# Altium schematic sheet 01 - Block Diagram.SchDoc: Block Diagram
size A3; PageSetup: Record=PageOptions¦CenterHorizontal=True¦CenterVertical=True¦PrintScale=0.70¦XCorrection=1.00¦YCorrection=1.00¦PrintKind=0¦BorderSize=5000000¦LeftOffset=0¦BottomOffset=0¦Orientation=2¦PaperLength=4200¦PaperWidth=2970¦Scale=100¦PaperSource=7¦PrintQuality=600¦MediaType=1¦DitherType=10¦PaperKind=A4¦PrintScaleMode=1; Author: Juan Anzola; SheetNumber: 1; SheetTotal: 20
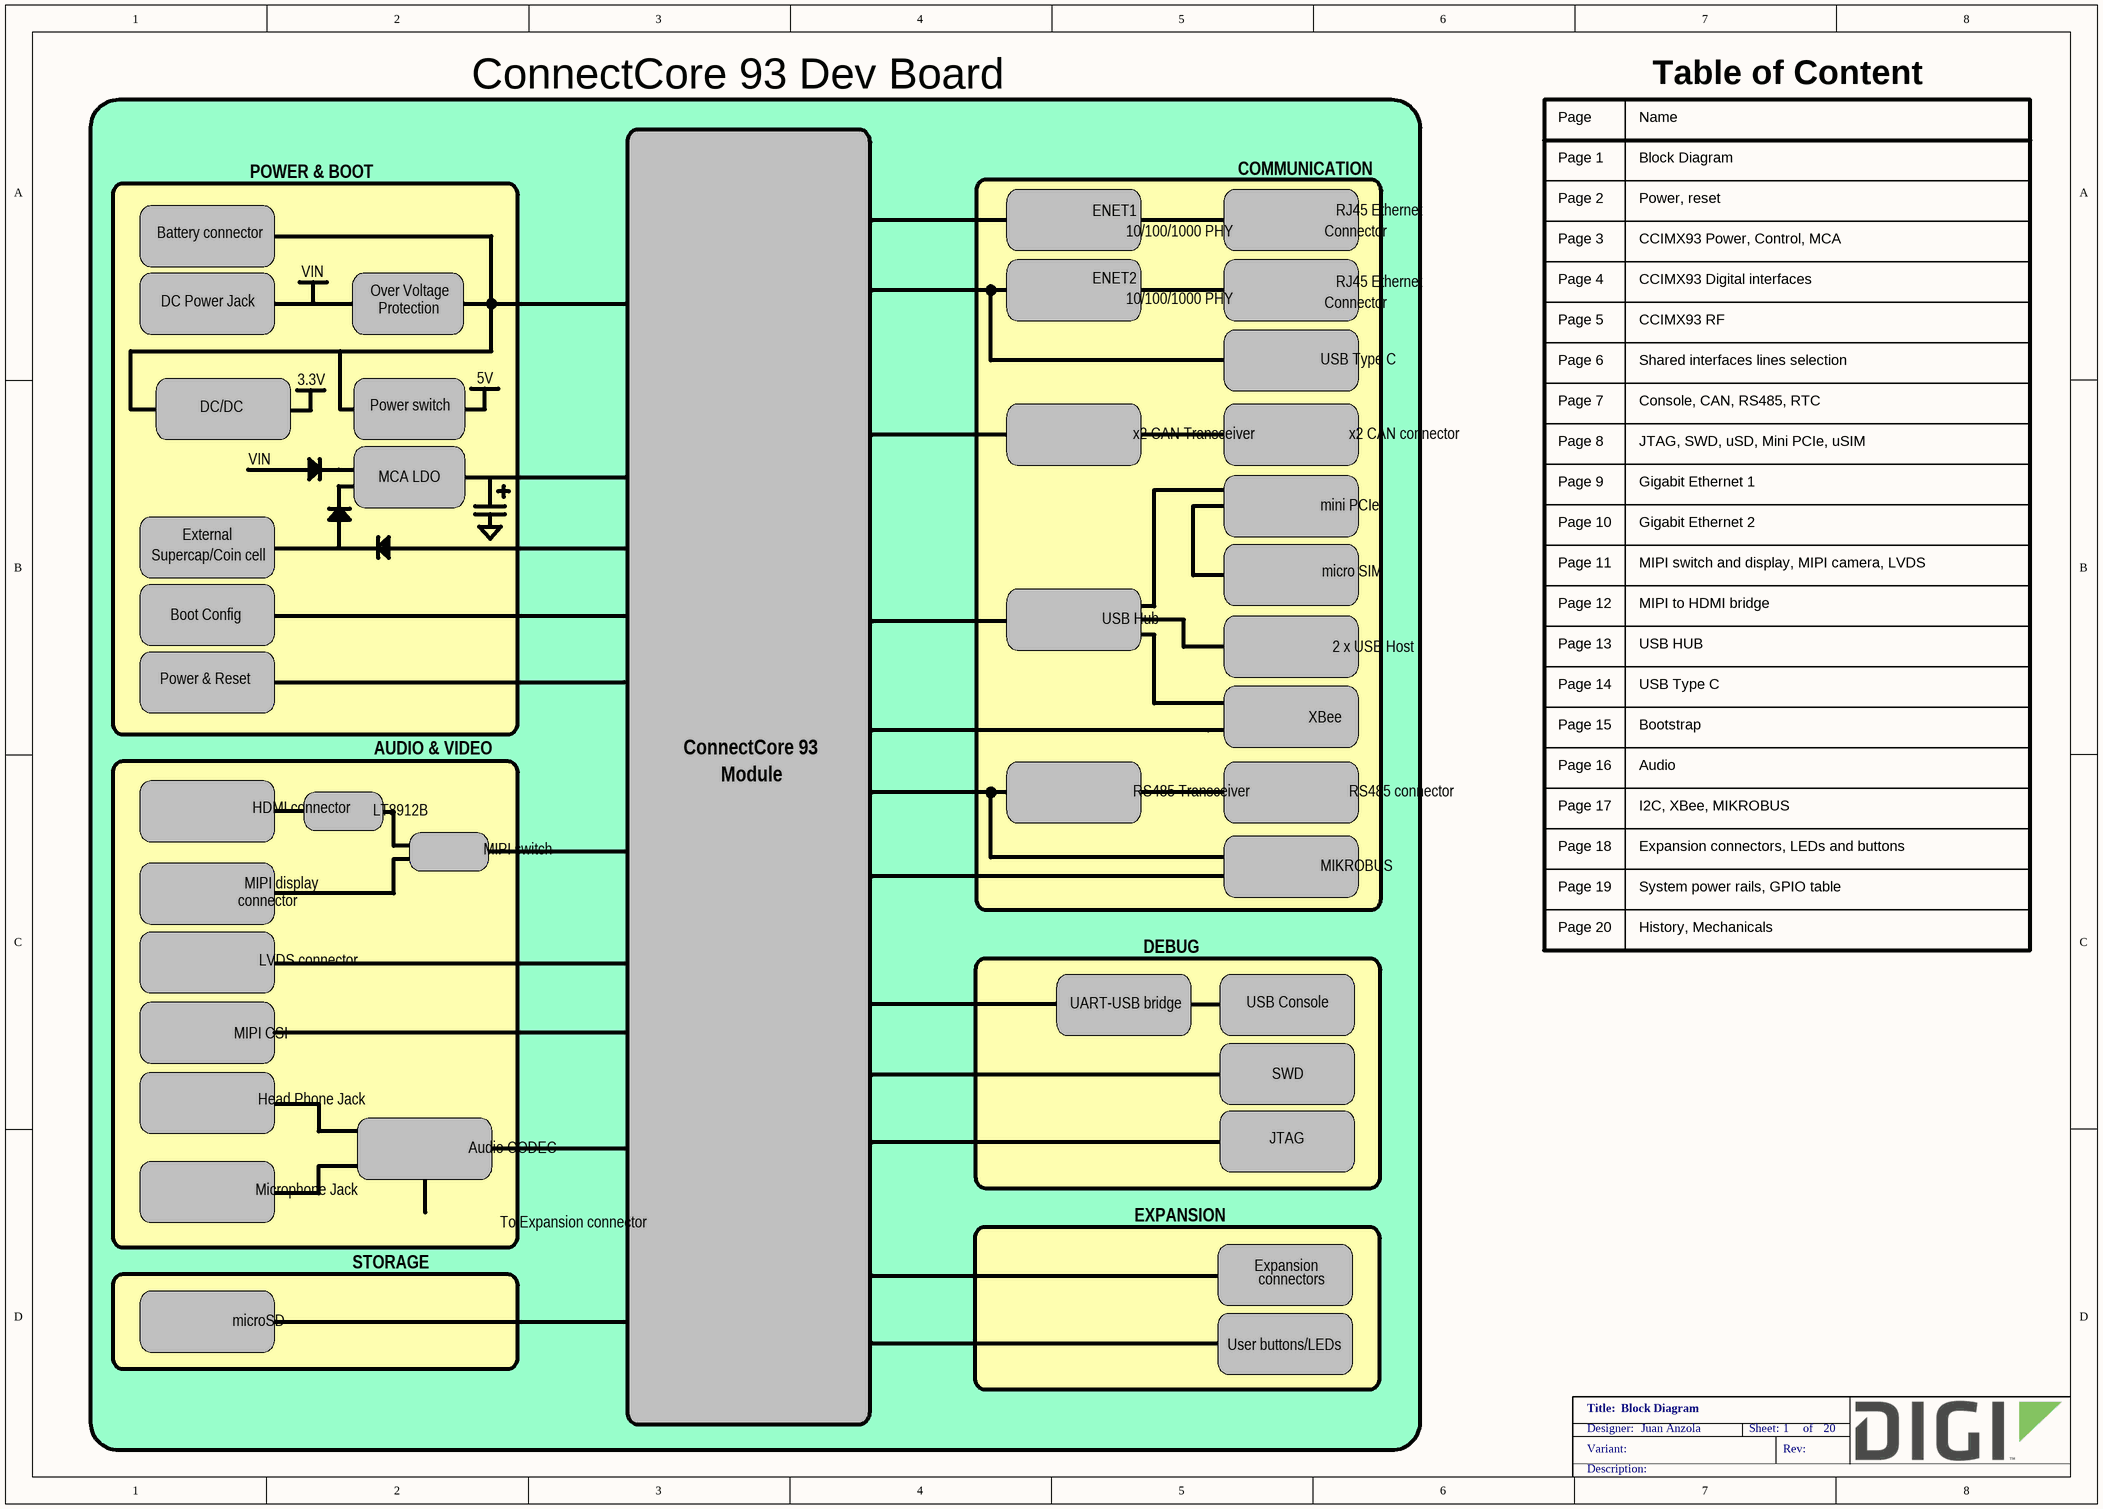
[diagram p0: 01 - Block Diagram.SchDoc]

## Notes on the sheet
- ConnectCore 93 Dev Board
- Table of Content
- POWER & BOOT
- COMMUNICATION
- Page 1
- Page
- Block Diagram
- Name
- Battery connector
- ENET1
- 10/100/1000 PHY
- Connector
- RJ45 Ethernet
- Page 2
- Page 3
- Power, reset
- CCIMX93 Power, Control, MCA
- DC Power Jack
- VIN
- Protection
- Over Voltage
- ENET2
- Page 4
- CCIMX93 Digital interfaces
- 5V
- USB Type C
- Page 5
- Page 6
- CCIMX93 RF
- Shared interfaces lines selection
- DC/DC
- 3.3V
- Power switch
- x2 CAN Transceiver
- x2 CAN connector
- Page 7
- Page 8
- JTAG, SWD, uSD, Mini PCIe, uSIM
- Console, CAN, RS485, RTC
- MCA LDO
- mini PCIe
- Page 9
- Gigabit Ethernet 1
- Supercap/Coin cell
- External
- micro SIM
- Page 10
- Page 11
- Gigabit Ethernet 2
- MIPI switch and display, MIPI camera, LVDS
- Boot Config
- USB Hub
- 2 x USB Host
- Page 12
- Page 13
- USB HUB
- MIPI to HDMI bridge
- Power & Reset
- XBee
- Page 14
- AUDIO & VIDEO
- ConnectCore 93
- Module
- Page 15
- Page 16
- Audio
- Bootstrap
- HDMI connector
- LT8912B
- MIPI switch
- RS485 Transceiver
- RS485 connector
- Page 17
- Page 18
- I2C, XBee, MIKROBUS
- Expansion connectors, LEDs and buttons
- connector
- MIPI display
- MIKROBUS
- Page 19
- System power rails, GPIO table
- LVDS connector
- DEBUG
- Page 20
- History, Mechanicals
- MIPI CSI
- UART-USB bridge
- USB Console
- Head Phone Jack
- SWD
- Audio CODEC
- JTAG
- Microphone Jack
- To Expansion connector
- EXPANSION
- microSD
- STORAGE
- Expansion
- connectors
- User buttons/LEDs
